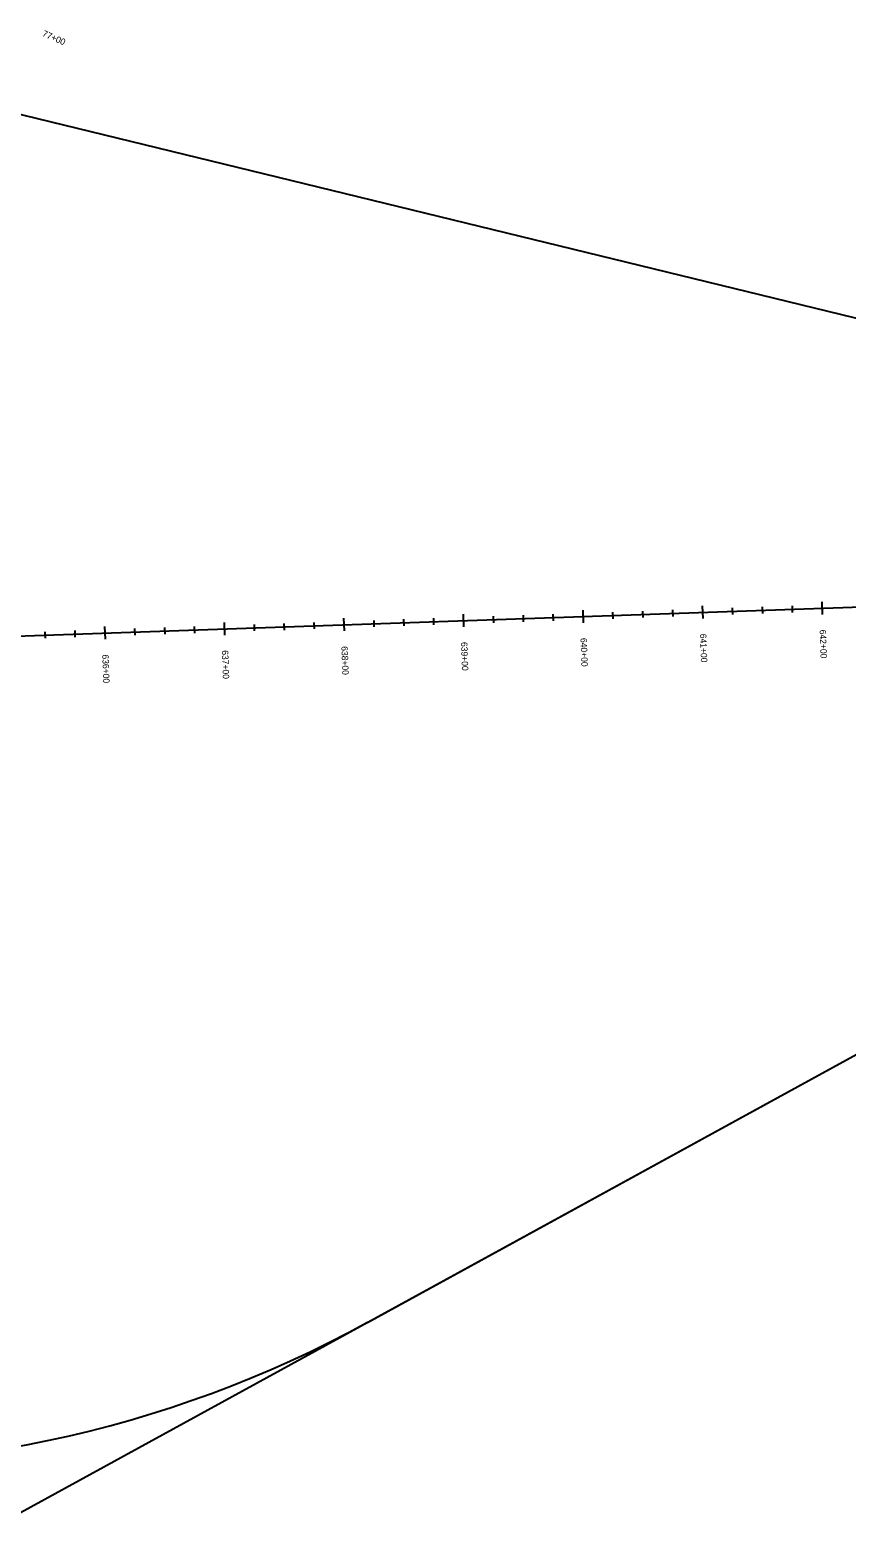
# Model space of a CAD drawing. Extents: x 2307903 to 2339201, y 758183 to 762824.
# Drawn here: x 2321238 to 2321920, y 759490 to 760751 of the extents above; entities that cross this region are included whole.
import ezdxf

# ---------------------------------------------------------------- set-up
doc = ezdxf.new("R2010")
doc.units = 0
for name, color, linetype in [('Default', 7, 'Continuous'), ('E_Terrain_Contour_Imported', 7, 'Continuous'), ('E_Terrain_Contour_Major', 7, 'Continuous'), ('E_Terrain_Hole', 7, 'Continuous'), ('E_Terrain_Island', 7, 'Continuous'), ('Geom_Baseline', 7, 'Continuous')]:
    doc.layers.add(name, color=color, linetype=linetype)

msp = doc.modelspace()

# ---------------------------------------------------------------- linework, layer by layer
at = {"layer": 'Default'}
for p, q in [((2320277.7, 760211.3), (2324007.2, 760340.3)), ((2321599.7, 760262.4), (2321600.1, 760251.8)), ((2321649.8, 760261.5), (2321650, 760256)), ((2321674.8, 760262.4), (2321675, 760256.9)), ((2321699.7, 760265.8), (2321700, 760255.2)), ((2321724.7, 760264.1), (2321724.9, 760258.6)), ((2321749.7, 760265), (2321749.9, 760259.5)), ((2321774.7, 760265.9), (2321774.9, 760260.3)), ((2321799.6, 760269.3), (2321800, 760258.7)), ((2321824.7, 760267.6), (2321824.9, 760262.1)), ((2321849.7, 760268.5), (2321849.9, 760262.9)), ((2321874.7, 760269.3), (2321874.8, 760263.8)), ((2321899.5, 760272.8), (2321899.9, 760262.1)), ((2321275, 760248.6), (2321275.2, 760243.1)), ((2321299.9, 760252), (2321300.3, 760241.4)), ((2321325, 760250.3), (2321325.2, 760244.8)), ((2321350, 760251.2), (2321350.2, 760245.7)), ((2321374.9, 760252), (2321375.1, 760246.5)), ((2321399.8, 760255.5), (2321400.2, 760244.9)), ((2321424.9, 760253.8), (2321425.1, 760248.3)), ((2321449.9, 760254.6), (2321450.1, 760249.1)), ((2321474.9, 760255.5), (2321475.1, 760250)), ((2321499.8, 760258.9), (2321500.2, 760248.3)), ((2321524.9, 760257.2), (2321525.1, 760251.7)), ((2321549.8, 760258.1), (2321550, 760252.6)), ((2321574.8, 760259), (2321575, 760253.4)), ((2321624.8, 760260.7), (2321625, 760255.2)), ((2321250, 760247.7), (2321250.2, 760242.2)), ((2321191, 759489.6), (2322195.4, 760040.5))]:
    msp.add_line(p, q, dxfattribs=at)
at = {"layer": 'E_Terrain_Contour_Imported'}
for p, q in [((2321649.8, 760261.5), (2321650, 760256)), ((2321674.8, 760262.4), (2321675, 760256.9)), ((2321724.7, 760264.1), (2321724.9, 760258.6)), ((2321749.7, 760265), (2321749.9, 760259.5)), ((2321774.7, 760265.9), (2321774.9, 760260.3)), ((2321824.7, 760267.6), (2321824.9, 760262.1)), ((2321849.7, 760268.5), (2321849.9, 760262.9)), ((2321874.7, 760269.3), (2321874.8, 760263.8)), ((2321275, 760248.6), (2321275.2, 760243.1)), ((2321325, 760250.3), (2321325.2, 760244.8)), ((2321350, 760251.2), (2321350.2, 760245.7)), ((2321374.9, 760252), (2321375.1, 760246.5)), ((2321424.9, 760253.8), (2321425.1, 760248.3)), ((2321449.9, 760254.6), (2321450.1, 760249.1)), ((2321474.9, 760255.5), (2321475.1, 760250)), ((2321524.9, 760257.2), (2321525.1, 760251.7)), ((2321549.8, 760258.1), (2321550, 760252.6)), ((2321574.8, 760259), (2321575, 760253.4)), ((2321624.8, 760260.7), (2321625, 760255.2)), ((2321250, 760247.7), (2321250.2, 760242.2))]:
    msp.add_line(p, q, dxfattribs=at)
at = {"layer": 'E_Terrain_Hole'}
msp.add_line((2321519.8, 759669.9), (2322195.4, 760040.5), dxfattribs=at)
msp.add_arc((2321052.4, 760522.2), 972, 264.9768, 298.7415, dxfattribs=at)
msp.add_arc((2321052.4, 760522.2), 972, 264.9768, 298.7415, dxfattribs=at)
at = {"layer": 'E_Terrain_Island'}
for p, q in [((2321599.7, 760262.4), (2321600.1, 760251.8)), ((2321699.7, 760265.8), (2321700, 760255.2)), ((2321799.6, 760269.3), (2321800, 760258.7)), ((2321899.5, 760272.8), (2321899.9, 760262.1)), ((2321299.9, 760252), (2321300.3, 760241.4)), ((2321399.8, 760255.5), (2321400.2, 760244.9)), ((2321499.8, 760258.9), (2321500.2, 760248.3))]:
    msp.add_line(p, q, dxfattribs=at)
at = {"layer": 'Geom_Baseline'}
for p, q in [((2321201.9, 760687.3), (2322018.2, 760488)), ((2320277.7, 760211.3), (2324007.2, 760340.3))]:
    msp.add_line(p, q, dxfattribs=at)

# ---------------------------------------------------------------- texts
at = {"layer": 'E_Terrain_Contour_Major'}
for s, rotation, p in [('77+00', 336.2923, (2321247.4, 760746.2)), ('642+00', 271.9805, (2321897.7, 760249.3)), ('639+00', 271.9805, (2321597.9, 760239)), ('640+00', 271.9805, (2321697.8, 760242.4)), ('641+00', 271.9805, (2321797.7, 760245.9)), ('636+00', 271.9805, (2321298, 760228.6)), ('637+00', 271.9805, (2321398, 760232.1)), ('638+00', 271.9805, (2321497.9, 760235.5))]:
    msp.add_text(s, height=5.34, rotation=rotation, dxfattribs=at).set_placement(p)

doc.saveas('drawing.dxf')
